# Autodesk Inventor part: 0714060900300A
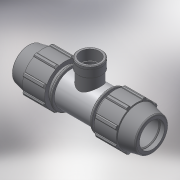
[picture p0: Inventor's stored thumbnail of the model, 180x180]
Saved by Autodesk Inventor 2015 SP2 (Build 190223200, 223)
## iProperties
Created: 2017-02
Part Number: 0714060900300A
Material: Generic
Description: PLASSON TEE WITH THREADED FEMALE OFFTAKE 90-3."-90
Document SubType Name: Modeling
Designer: KIM
Mass: 92.6774 g
Surface Area: 199.44 cm^2
Volume: 66.1981 cm^3
Density: 1 g/cm^3
Appearance: Default
Author: KIM
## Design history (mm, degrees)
derived "87140.ipt"
feature "Solid1::87140.ipt"
feature "Solid2::87140.ipt"
tag "TaggingFeature1"
body "Solid1"
other parameters: "d4" = 17.45833, "d5" = 50.28, "d7" = 154, "d11" = 6.98333, "d13" = 120 deg, "d14" = 117, "d15" = 10 deg, "d16" = 133.98, "d18" = 4.5, "d19" = 35 deg, "d20" = 17.5 deg, "d21" = 143.22, "d23" = 0, "d25" = 360 deg, "d27" = 3.08, "d33" = 1.8, "d42" = 75.42, "d43" = 4.62, "d46" = 2.7, "d68" = 12.57, "d72" = 116, "d76" = 84.926, "d80" = 2.54778, "d91" = 115.5, "d93" = 165, "d95" = 81, "d115" = 106.1575, "d116" = 135 deg, "d117" = 97.6649, "d118" = 419, "d119" = 81, "d121" = 0, "d122" = 81, "d124" = 0, "d128" = 0, "d129" = 9, "d130" = 12, "d131" = 0.3, "d132" = 0.3, "d133" = 106.1575, "E_" = 154, "A_" = 116, "l_" = 165, "Rp_" = 84.926, "H_" = 419
